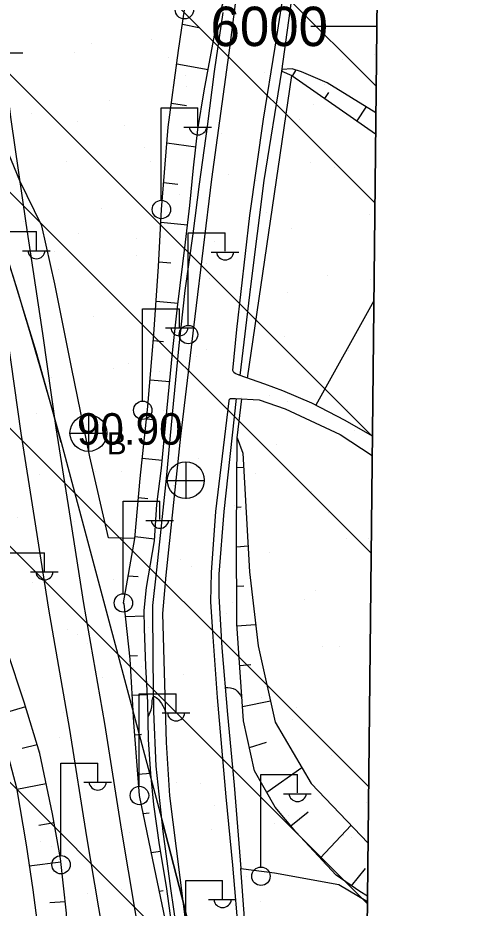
# Model space of a CAD drawing. Extents: x 417995 to 421451, y 4454518 to 4458015.
# Drawn here: x 421208.7 to 421295.4, y 4455832.3 to 4456001.6 of the extents above; entities that cross this region are included whole.
import ezdxf

# ---------------------------------------------------------------- set-up
doc = ezdxf.new("R2010")
doc.units = 0
for name, color, linetype in [('ADAKENARI', 7, 'Continuous'), ('Default', 7, 'Continuous'), ('Egri_1m', 7, 'Continuous'), ('P_Grid', 7, 'Continuous'), ('PAFTALAMA', 7, 'Continuous'), ('PL_AYA_BOLGE_PARKI', 7, 'Continuous'), ('PL_AYA_PARK_DINLENME', 7, 'Continuous'), ('S_Elektrik_Diregi', 7, 'Continuous'), ('S_Rogar_Kapagi', 7, 'Continuous'), ('S_Rogar_Kapagi_Buski', 7, 'Continuous'), ('Sev_Sevalti', 7, 'Continuous'), ('Sev_Sevustu', 7, 'Continuous'), ('Sev_Tarama', 7, 'Continuous'), ('Sinir_itirazli_Mulkiyet', 7, 'Continuous'), ('Sinir_Tel_bir_taraf', 7, 'Continuous'), ('SN_TR_SIVILASMA', 7, 'Continuous'), ('TR_PARKALANI', 7, 'Continuous'), ('Y_Kot_Noktasi', 7, 'Continuous'), ('Y_Lejant', 7, 'Continuous'), ('Yol_Kaldirim_kenari_bordurtasi', 7, 'Continuous'), ('Yol_Sose', 7, 'Continuous'), ('Yol_Toprak_Duz', 7, 'Continuous'), ('Yol_Toprak_Kesik', 7, 'Continuous')]:
    doc.layers.add(name, color=color, linetype=linetype)

# ---------------------------------------------------------------- blocks, each defined once
blk = doc.blocks.new('POINT_DISPLAY')
at = {"layer": 'Default'}
blk.add_line((0, 0), (0, 0), dxfattribs=at)

msp = doc.modelspace()

# ---------------------------------------------------------------- linework, layer by layer
at = {"layer": 'ADAKENARI'}
for p, q in [((421216.89, 4455920.89), (421236.23, 4455848.47)), ((421240.3, 4455832.49), (421236.23, 4455848.47)), ((421243.98, 4455816.42), (421240.3, 4455832.49))]:
    msp.add_line(p, q, dxfattribs=at)
msp.add_arc((420434.01, 4455711.76), 810.32, 14.95584, 31.47684, dxfattribs=at)
at = {"layer": 'Egri_1m'}
for points in [[(421248.03, 4455874.27), (421249.99, 4455873.86), (421251.24, 4455872.35)], [(421233.41, 4455868.7), (421234.1, 4455870.58), (421234.47, 4455872.54), (421235.97, 4455871.22), (421236.7, 4455869.64)]]:
    msp.add_spline(points, degree=3, dxfattribs=at)
at = {"layer": 'P_Grid'}
msp.add_line((421276.84, 4456000), (421264.34, 4456000), dxfattribs=at)
at = {"layer": 'PAFTALAMA'}
for p, q in [((421266.41, 4454999.4), (421295.36, 4457775.52)), ((421276.84, 4456000), (421264.34, 4456000))]:
    msp.add_line(p, q, dxfattribs=at)
at = {"layer": 'PL_AYA_BOLGE_PARKI'}
msp.add_line((421271.52, 4455489.32), (421283.96, 4456682.26), dxfattribs=at)
msp.add_lwpolyline([(421216.89, 4455920.89), (421236.23, 4455848.47), (421240.3, 4455832.49), (421243.98, 4455816.42), (421247.29, 4455800.26), (421250.21, 4455784.03), (421252.74, 4455767.74), (421254.89, 4455751.39), (421256.64, 4455734.99), (421258.01, 4455718.56), (421258.99, 4455702.09), (421259.58, 4455685.61), (421259.77, 4455669.13), (421259.58, 4455652.64), (421258.99, 4455636.16), (421258.01, 4455619.7), (421256.64, 4455603.26), (421254.88, 4455586.87), (421252.74, 4455570.52), (421250.21, 4455554.22), (421247.29, 4455537.99), (421243.98, 4455521.84), (421240.3, 4455505.76), (421271.52, 4455489.32)], dxfattribs=at)
msp.add_arc((420434.01, 4455711.76), 810.32, 14.95584, 31.47684, dxfattribs=at)
at = {"layer": 'PL_AYA_PARK_DINLENME'}
msp.add_lwpolyline([(421188.93, 4456006.25), (421195.28, 4455989.43), (421201.25, 4455972.48), (421206.84, 4455955.4), (421212.06, 4455938.2), (421216.89, 4455920.89), (421236.23, 4455848.47), (421240.3, 4455832.49), (421243.98, 4455816.42), (421247.29, 4455800.26), (421250.21, 4455784.03), (421252.74, 4455767.74), (421254.89, 4455751.39), (421256.64, 4455734.99), (421258.01, 4455718.56), (421258.99, 4455702.09)], dxfattribs=at)
at = {"layer": 'S_Elektrik_Diregi'}
for p, q in [((421204.34, 4455995), (421209.59, 4455995)), ((421235.89, 4455967), (421235.89, 4455984.5)), ((421235.89, 4455984.5), (421242.89, 4455984.5)), ((421242.89, 4455981), (421242.89, 4455984.5)), ((421240.23, 4455980.86), (421245.48, 4455980.86)), ((421205.19, 4455960.96), (421212.19, 4455960.96)), ((421212.19, 4455957.46), (421212.19, 4455960.96)), ((421241.05, 4455943.23), (421241.05, 4455960.73)), ((421241.05, 4455960.73), (421248.05, 4455960.73)), ((421248.05, 4455957.23), (421248.05, 4455960.73)), ((421209.53, 4455957.32), (421214.78, 4455957.32)), ((421245.39, 4455957.09), (421250.64, 4455957.09)), ((421232.36, 4455928.81), (421232.36, 4455946.31)), ((421232.36, 4455946.31), (421239.36, 4455946.31)), ((421239.36, 4455942.81), (421239.36, 4455946.31)), ((421236.7, 4455942.67), (421241.95, 4455942.67)), ((421228.67, 4455892.18), (421228.67, 4455909.68)), ((421228.67, 4455909.68), (421235.67, 4455909.68)), ((421235.67, 4455906.18), (421235.67, 4455909.68)), ((421233.01, 4455906.04), (421238.26, 4455906.04)), ((421206.71, 4455899.87), (421213.71, 4455899.87)), ((421213.71, 4455896.37), (421213.71, 4455899.87)), ((421211.05, 4455896.23), (421216.3, 4455896.23)), ((421231.73, 4455855.55), (421231.73, 4455873.05)), ((421231.73, 4455873.05), (421238.73, 4455873.05)), ((421238.73, 4455869.55), (421238.73, 4455873.05)), ((421236.07, 4455869.41), (421241.32, 4455869.41)), ((421216.84, 4455842.38), (421216.84, 4455859.88)), ((421216.84, 4455859.88), (421223.84, 4455859.88)), ((421223.84, 4455856.38), (421223.84, 4455859.88)), ((421254.82, 4455840.2), (421254.82, 4455857.7)), ((421254.82, 4455857.7), (421261.82, 4455857.7)), ((421261.82, 4455854.2), (421261.82, 4455857.7)), ((421221.18, 4455856.24), (421226.43, 4455856.24)), ((421259.16, 4455854.06), (421264.41, 4455854.06)), ((421240.57, 4455820.04), (421240.57, 4455837.54)), ((421240.57, 4455837.54), (421247.57, 4455837.54)), ((421247.57, 4455834.04), (421247.57, 4455837.54)), ((421244.91, 4455833.9), (421250.16, 4455833.9))]:
    msp.add_line(p, q, dxfattribs=at)
for centre in [(421240.31, 4456003.17), (421235.93, 4455965.17), (421241.08, 4455941.39), (421232.39, 4455926.98), (421228.71, 4455890.34), (421231.77, 4455853.71), (421216.87, 4455840.55), (421254.85, 4455838.36)]:
    msp.add_circle(centre, 1.75, dxfattribs=at)
for centre in [(421242.9, 4455981.02), (421212.19, 4455957.48), (421248.05, 4455957.24), (421239.36, 4455942.83), (421235.67, 4455906.19), (421213.72, 4455896.39), (421238.73, 4455869.56), (421223.84, 4455856.4), (421261.82, 4455854.21), (421247.57, 4455834.05)]:
    msp.add_arc(centre, 1.66, 184.8384, 355.1464, dxfattribs=at)
at = {"layer": 'S_Rogar_Kapagi'}
for p, q in [((421240.62, 4455910.17), (421240.62, 4455917.17)), ((421237.05, 4455913.63), (421244.05, 4455913.63))]:
    msp.add_line(p, q, dxfattribs=at)
msp.add_circle((421240.56, 4455913.69), 3.5, dxfattribs=at)
at = {"layer": 'S_Rogar_Kapagi_Buski'}
for p, q in [((421222.07, 4455926.16), (421222.07, 4455919.16)), ((421218.57, 4455922.66), (421225.57, 4455922.66))]:
    msp.add_line(p, q, dxfattribs=at)
msp.add_circle((421222.07, 4455922.66), 3.5, dxfattribs=at)
at = {"layer": 'Sev_Sevalti'}
for points in [[(421238.37, 4455825.84), (421236.91, 4455836.38), (421235.56, 4455844.34), (421234.48, 4455852.03), (421233.96, 4455857.81), (421233.49, 4455864.36), (421233.36, 4455871.37), (421232.97, 4455878.32), (421232.72, 4455885.47), (421232.69, 4455888.92), (421233.12, 4455893.26), (421234.6, 4455902.15), (421235.06, 4455909.06), (421235.96, 4455915.99), (421236.98, 4455926.81), (421238.14, 4455938.54), (421239.02, 4455946.57), (421240.5, 4455958.95), (421241.37, 4455965.94), (421242.06, 4455973.12), (421242.88, 4455980.36), (421244.09, 4455987.73), (421246.22, 4455999.35), (421248, 4456005.73)], [(421276.67, 4455983.55), (421267.44, 4455989.28), (421262.58, 4455991.39), (421260.77, 4455991.95), (421258.85, 4455991.79), (421258.81, 4455991.48)], [(421250.31, 4455921.72), (421251.43, 4455918.85), (421252.66, 4455896.27), (421254.31, 4455882.21), (421257.53, 4455867.65), (421264.39, 4455856.02), (421275.22, 4455844.64)], [(421200.04, 4455901.3), (421198.77, 4455892.77), (421198.82, 4455888.93), (421199.82, 4455883.77), (421202.59, 4455874.89), (421205.73, 4455865.28), (421208.42, 4455855.14), (421210.27, 4455844.32), (421211.48, 4455835.75), (421212.8, 4455826.09), (421213.4, 4455815.54), (421212.57, 4455803.64)]]:
    msp.add_lwpolyline(points, dxfattribs=at)
at = {"layer": 'Sev_Sevustu'}
for points in [[(421238.37, 4455825.84), (421236.97, 4455828.73), (421234.3, 4455841.48), (421231.77, 4455853.73), (421230.69, 4455867.57), (421229.99, 4455879.64), (421228.88, 4455890.14), (421228.71, 4455890.36), (421230.91, 4455902.6), (421231.9, 4455914), (421233.36, 4455927.7), (421234.51, 4455941.48), (421235.38, 4455954.35), (421235.93, 4455965.18), (421237.24, 4455980.84), (421239.21, 4455995.42), (421240.31, 4456003.18)], [(421258.81, 4455991.48), (421260.7, 4455990.64), (421276.63, 4455979.58)], [(421275.12, 4455834.56), (421273.61, 4455835.47), (421269.12, 4455838.57), (421261.48, 4455846.81), (421257.57, 4455851.52), (421253.61, 4455858.43), (421251.54, 4455867.9), (421250.28, 4455886.37), (421250.23, 4455903.54), (421250.31, 4455921.72)], [(421217.66, 4455803.58), (421218.43, 4455820.44), (421217.92, 4455831.33), (421216.74, 4455841.72), (421215.27, 4455850.22), (421212.86, 4455861.7), (421209.85, 4455871.46), (421206.66, 4455881.26), (421203.78, 4455887.78), (421201.98, 4455892.42), (421201.25, 4455896.88), (421200.04, 4455901.3)]]:
    msp.add_lwpolyline(points, dxfattribs=at)
at = {"layer": 'Sev_Tarama'}
for p, q in [((421239.92, 4456000.42), (421243.05, 4455999.79)), ((421238.87, 4455992.88), (421244.84, 4455991.83)), ((421260.84, 4455990.55), (421261.53, 4455991.71)), ((421266.97, 4455986.29), (421267.72, 4455987.46)), ((421237.86, 4455985.39), (421240.71, 4455984.93)), ((421273.12, 4455982.02), (421274.87, 4455984.67)), ((421236.99, 4455977.85), (421242.51, 4455977.08)), ((421236.36, 4455970.31), (421239.04, 4455969.98)), ((421235.81, 4455962.75), (421240.91, 4455962.24)), ((421235.43, 4455955.24), (421237.72, 4455955.02)), ((421234.93, 4455947.75), (421239.11, 4455947.35)), ((421234.41, 4455940.27), (421236.35, 4455940.08)), ((421233.78, 4455932.8), (421237.54, 4455932.43)), ((421233.11, 4455925.33), (421234.96, 4455925.15)), ((421232.31, 4455917.88), (421236.1, 4455917.5)), ((421250.29, 4455916.07), (421251.58, 4455916.16)), ((421231.59, 4455910.42), (421233.39, 4455910.23)), ((421250.26, 4455908.55), (421251.12, 4455908.61)), ((421230.94, 4455902.97), (421234.62, 4455902.56)), ((421250.24, 4455901.04), (421252.39, 4455901.18)), ((421229.63, 4455895.49), (421231.54, 4455895.34)), ((421250.26, 4455893.53), (421251.61, 4455893.61)), ((421229.13, 4455887.75), (421232.7, 4455887.9)), ((421250.3, 4455885.98), (421253.84, 4455886.26)), ((421229.92, 4455880.29), (421231.41, 4455880.34)), ((421250.82, 4455878.43), (421252.94, 4455878.65)), ((421230.39, 4455872.79), (421233.28, 4455872.92)), ((421251.35, 4455870.67), (421256.64, 4455871.69)), ((421210.12, 4455870.57), (421204.54, 4455868.93)), ((421230.87, 4455865.28), (421232.17, 4455865.35)), ((421212.36, 4455863.32), (421209.49, 4455862.62)), ((421252.65, 4455862.81), (421255.92, 4455863.83)), ((421255.96, 4455854.34), (421262.62, 4455859.02)), ((421231.45, 4455857.78), (421233.95, 4455857.95)), ((421214.07, 4455855.93), (421208.47, 4455854.83)), ((421232.48, 4455850.28), (421233.59, 4455850.41)), ((421260.52, 4455847.97), (421263.8, 4455850.58)), ((421215.57, 4455848.52), (421212.64, 4455848.03)), ((421266.13, 4455841.79), (421271.97, 4455848.06)), ((421234.01, 4455842.87), (421235.77, 4455843.13)), ((421216.82, 4455841.05), (421210.84, 4455840.28)), ((421272.07, 4455836.54), (421274.72, 4455839.83)), ((421235.56, 4455835.49), (421236.28, 4455835.62)), ((421217.68, 4455833.48), (421214.76, 4455833.27))]:
    msp.add_line(p, q, dxfattribs=at)
at = {"layer": 'Sinir_itirazli_Mulkiyet'}
for points in [[(421252.3, 4455933.11), (421260.7, 4455990.64)], [(421276.3, 4455947.83), (421265.25, 4455927.95)], [(421250.31, 4455921.72), (421251.25, 4455929.17)]]:
    msp.add_lwpolyline(points, dxfattribs=at)
at = {"layer": 'Sinir_Tel_bir_taraf'}
for points in [[(421258.81, 4455991.48), (421260.93, 4456006.72), (421264.7, 4456031.48), (421265.79, 4456040.28), (421266.69, 4456050.38), (421267.14, 4456059.5), (421267.65, 4456070.54), (421268.28, 4456085.43), (421268.71, 4456099.17), (421268.94, 4456109.08), (421268.86, 4456117.84), (421269.06, 4456132.65), (421272.74, 4456132.94)], [(421230.91, 4455902.6), (421225.87, 4455902.74), (421222.37, 4455918.12), (421218.87, 4455935.2), (421215.66, 4455951.02), (421213.21, 4455962.06), (421209.06, 4455970.62), (421198.91, 4455995.24), (421192.37, 4456010.82), (421184.68, 4456029.28), (421178.12, 4456045.91), (421171.29, 4456061.51), (421163.79, 4456075.27), (421155.39, 4456089.68), (421147.08, 4456103.8), (421143.47, 4456109.74)], [(421247.6, 4456002.64), (421245.99, 4455991.43), (421244.66, 4455980.97), (421243.14, 4455969.99), (421241.9, 4455960.52), (421240.42, 4455949.76), (421239.26, 4455939.32), (421237.96, 4455926.26), (421236.82, 4455914.03), (421235.69, 4455903.18), (421235.01, 4455896.66), (421234.25, 4455889.86), (421234.33, 4455879.41), (421234.45, 4455869.67), (421234.91, 4455859.26), (421236.21, 4455846.87), (421237.65, 4455836.05), (421239.38, 4455824.21), (421241.86, 4455806.44), (421242.28, 4455803.33)], [(421254.01, 4455803.2), (421253.34, 4455809.87), (421251.74, 4455830.4), (421251, 4455839.84), (421257.45, 4455838.98), (421269.62, 4455836.78), (421275.11, 4455833.55)]]:
    msp.add_lwpolyline(points, dxfattribs=at)
at = {"layer": 'SN_TR_SIVILASMA'}
for p, q in [((421276.73, 4455988.66), (419957.49, 4457307.89)), ((421276.49, 4455966.44), (419971.97, 4457270.96)), ((421276.03, 4455922), (420004.05, 4457193.98)), ((421275.8, 4455899.78), (420015.35, 4457160.22)), ((421275.33, 4455855.34), (420037.81, 4457092.87)), ((421275.1, 4455833.12), (420049.03, 4457059.2)), ((421274.64, 4455788.69), (420075.79, 4456987.53))]:
    msp.add_line(p, q, dxfattribs=at)
at = {"layer": 'Y_Lejant'}
msp.add_lwpolyline([(419168.18, 4457798.01), (421295.36, 4457775.52), (421266.41, 4454999.4), (419138.44, 4455021.89)], close=True, dxfattribs=at)
at = {"layer": 'Yol_Kaldirim_kenari_bordurtasi'}
for points in [[(421250.88, 4455933.61), (421252.94, 4455950.51), (421255.47, 4455970.72), (421258.81, 4455991.48)], [(421250.13, 4455929.23), (421247.81, 4455907.75), (421246.85, 4455895.79), (421246.88, 4455891.61), (421247.4, 4455881.78), (421248.47, 4455869.11), (421249.79, 4455855.67), (421251, 4455839.84)]]:
    msp.add_lwpolyline(points, dxfattribs=at)
at = {"layer": 'Yol_Sose'}
for points in [[(421250.72, 4455933.67), (421249.94, 4455933.97), (421249.67, 4455934.16), (421249.5, 4455934.57), (421250.25, 4455942.34), (421252.72, 4455964.06), (421255.35, 4455982.37), (421257.58, 4455996.07), (421260.02, 4456011.89), (421262.71, 4456029.43), (421264.19, 4456040.52), (421265.09, 4456052.77), (421265.62, 4456064.09), (421266.51, 4456085.34), (421267.13, 4456105.67), (421267.38, 4456116.81), (421267.05, 4456131.64), (421267.21, 4456131.96), (421267.66, 4456132.5)], [(421228.15, 4455803.47), (421225.57, 4455823.33), (421221.76, 4455845.82), (421218.54, 4455866.28), (421214.57, 4455889.16), (421211.81, 4455906.6), (421209.3, 4455922.65), (421206.77, 4455940.63), (421203.57, 4455961.62), (421200.71, 4455981.38), (421198.08, 4456001.68), (421195.05, 4456023.62), (421191.88, 4456047.06), (421189.51, 4456065.97), (421187.45, 4456081.21), (421183.02, 4456108.72)], [(421234.93, 4455803.4), (421232.22, 4455824.32), (421228.39, 4455846.9), (421225.17, 4455867.38), (421221.19, 4455890.26), (421218.45, 4455907.65), (421215.94, 4455923.64), (421213.41, 4455941.61), (421210.22, 4455962.6), (421207.37, 4455982.29), (421204.74, 4456002.58), (421201.7, 4456024.53), (421198.54, 4456047.92), (421196.17, 4456066.84), (421194.09, 4456082.19), (421189.82, 4456108.77)], [(421252.67, 4456025.65), (421248.93, 4455996.36), (421245.44, 4455970.97), (421242.31, 4455944.84), (421239.58, 4455922.06), (421236.75, 4455895.62), (421236.15, 4455888.34), (421236.87, 4455863.82), (421237.47, 4455853.63), (421240.69, 4455828.11), (421244.23, 4455803.3)], [(421252.95, 4455803.21), (421252.03, 4455811.61), (421250.72, 4455826.36), (421249.48, 4455840.43), (421248.24, 4455853.48), (421246.61, 4455872.36), (421245.75, 4455883.91), (421245.36, 4455890.55), (421245.43, 4455896.12), (421246.31, 4455907.75), (421248.79, 4455928.8), (421248.89, 4455929.08), (421249.08, 4455929.23), (421250.04, 4455929.23)]]:
    msp.add_lwpolyline(points, dxfattribs=at)
at = {"layer": 'Yol_Toprak_Duz'}
msp.add_lwpolyline([(421250.04, 4455929.23), (421254.53, 4455928.99), (421259.45, 4455927.29), (421269.9, 4455922.35), (421275.99, 4455918.41)], dxfattribs=at)
at = {"layer": 'Yol_Toprak_Kesik'}
msp.add_lwpolyline([(421276.03, 4455922.03), (421270.85, 4455925.05), (421264.53, 4455928.32), (421258.98, 4455930.67), (421255.57, 4455931.96), (421250.72, 4455933.67)], dxfattribs=at)

# ---------------------------------------------------------------- block references
at = {"layer": 'TR_PARKALANI', "xscale": 0.1, "yscale": 0.10000000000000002}
for p in [(421248.88, 4456000.16), (421222.58, 4455996.67), (421234.11, 4455997.55), (421252.99, 4455996.39), (421219.34, 4455994.95), (421276.35, 4455994.71), (421237.35, 4455994.07), (421270.32, 4455993.78), (421255.54, 4455991.18), (421240.51, 4455990.75), (421240.77, 4455988.57), (421266.89, 4455988.86), (421226, 4455985.97), (421264.86, 4455985.07), (421211.23, 4455983.36), (421219.97, 4455981.9), (421229.02, 4455981.11), (421262.2, 4455982.2), (421247.43, 4455979.59), (421232.66, 4455976.99), (421217.89, 4455974.38), (421233.87, 4455974.37), (421264.29, 4455974.09), (421268.87, 4455973.22), (421248.65, 4455971.77), (421254.09, 4455970.61), (421239.32, 4455968.01), (421224.55, 4455965.4), (421255.96, 4455964.55), (421275.53, 4455964.24), (421209.78, 4455962.8), (421220.13, 4455960.59), (421260.75, 4455961.63), (421231.27, 4455959.6), (421245.98, 4455959.03), (421215.63, 4455957.28), (421231.21, 4455956.42), (421216.44, 4455953.82), (421244.47, 4455954.91), (421245.17, 4455952.07), (421267.41, 4455952.65), (421275.59, 4455951.78), (421252.64, 4455950.05), (421259.95, 4455949.46), (421237.87, 4455947.44), (421223.1, 4455944.84), (421274.07, 4455943.67), (421259.3, 4455941.07), (421244.53, 4455938.46), (421242.57, 4455937.3), (421271.42, 4455938.36), (421229.76, 4455935.86), (421226.93, 4455934.98), (421235.58, 4455934.39), (421214.99, 4455933.25), (421265.96, 4455932.09), (421251.19, 4455929.48), (421256.47, 4455929.77), (421259.93, 4455928.72), (421236.42, 4455926.88), (421271.25, 4455927.16), (421212.13, 4455926.36), (421221.65, 4455924.27), (421224.09, 4455924.75), (421272.62, 4455923.11), (421257.85, 4455920.5), (421243.08, 4455917.9), (421212.84, 4455914.76), (421223.46, 4455915.28), (421228.31, 4455915.29), (421253.87, 4455915), (421238.23, 4455912.68), (421264.51, 4455911.52), (421249.74, 4455908.92), (421251.03, 4455908.2), (421208.66, 4455906.66), (421234.97, 4455906.31), (421267.77, 4455907.47), (421219.51, 4455905.78), (421271.17, 4455902.54), (421275.38, 4455902.52), (421256.4, 4455899.94), (421239.54, 4455898.56), (421241.63, 4455897.33), (421226.86, 4455894.73), (421211.39, 4455894.19), (421234.76, 4455892.98), (421265.17, 4455892.7), (421249.53, 4455890.38), (421263.06, 4455890.96), (421248.29, 4455888.35), (421218.05, 4455885.21), (421219.96, 4455884.36), (421233.52, 4455885.75), (421221.82, 4455882.59), (421266.49, 4455882), (421269.72, 4455881.98), (421254.95, 4455879.37), (421230.65, 4455878.04), (421232.15, 4455878.21), (421224.71, 4455876.24), (421240.18, 4455876.77), (421209.94, 4455873.63), (421255, 4455872.36), (421246.05, 4455870.68), (421217.36, 4455869.59), (421261.61, 4455870.39), (421246.84, 4455867.79), (421260.83, 4455868.08), (421216.6, 4455864.65), (421232.07, 4455865.18), (421212.93, 4455862.07), (421231.26, 4455862.06), (421268.27, 4455861.41), (421253.5, 4455858.81), (421223.26, 4455855.67), (421238.73, 4455856.2), (421243.45, 4455855.91), (421274.93, 4455852.43), (421246.1, 4455851.85), (421260.16, 4455849.83), (421228.65, 4455847.29), (421245.39, 4455847.22), (421257.35, 4455848.38), (421229.92, 4455846.69), (421270.45, 4455846.17), (421272.13, 4455845.77), (421213.01, 4455844.97), (421215.15, 4455844.09), (421266.82, 4455840.85), (421236.58, 4455837.71), (421252.05, 4455838.24), (421221.81, 4455835.11), (421228.38, 4455835.88), (421254.75, 4455833.61)]:
    msp.add_blockref('POINT_DISPLAY', p, dxfattribs=at)

# ---------------------------------------------------------------- texts
at = {"layer": 'PAFTALAMA'}
msp.add_text('6000', height=7.5, dxfattribs=at).set_placement((421245.27, 4455996.25))
at = {"layer": 'S_Rogar_Kapagi_Buski'}
msp.add_text('B', height=4.2, dxfattribs=at).set_placement((421225.57, 4455918.6))
at = {"layer": 'Y_Kot_Noktasi'}
msp.add_text('90.90', height=6, dxfattribs=at).set_placement((421219.89, 4455920.43))

doc.saveas('drawing.dxf')
